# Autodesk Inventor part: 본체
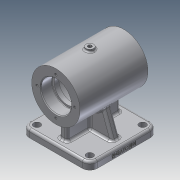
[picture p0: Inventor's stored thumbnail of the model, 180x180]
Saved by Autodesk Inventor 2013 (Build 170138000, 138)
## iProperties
Created: 2019-06
Part Number: 본체
Material: 알루미늄 6061
Document SubType Name: Modeling
Designer: user
Density: 2.71 g/cm^3
Mass: 612.634 g
Surface Area: 622.719 cm^2
Volume: 226.064 cm^3
Author: user
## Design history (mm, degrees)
sketch "스케치1"
  geometry: C1 r 32 at (0, 0); 1 further point
  constraints: 1 centre point, 1 coincident
  dimensions: "d0" = 64 diameter of C1
extrude "돌출1" new body sketch "스케치1" stored distance "d1" = 90; taper "d2" = 0 deg
sketch "스케치2"
  geometry: L1 (32, 45)-(-32, 45) reference; L2 (-32, -45)-(32, -45) reference; L3 (0, 45)-(0, -45); L4 (20, 45)-(20, 30); L5 (20, 30)-(17, 30); L6 (17, 30)-(17, 24); L7 (17, 24)-(25, 24); L8 (25, 24)-(25, -24); L9 (25, -24)-(17, -24); L10 (17, -24)-(17, -30); L11 (17, -30)-(20, -30); L12 (20, -30)-(20, -45); 1 further point
  constraints: 20 end point, 5 perpendicular, 4 parallel, 2 midpoint, 2 point on line
  dimensions: "d3" = 15 distance of L4.start L4.end; "d5" = 15 distance of L11.end L12.end; "d6" = 6 distance of L5.end L6.end; "d7" = 6 distance of L9.end L10.end; "d8" = 40 diameter of L4 L3; "d9" = 40 diameter of L12 L3; "d10" = 50 diameter of L8 L3; "d11" = 34 diameter of L6 L3; "d12" = 34 diameter of L10 L3
revolve "회전1" sketch "스케치2" stored, may be unused: angle "d13" = 90 deg
chamfer "모따기1" distance "d14" = 1; stored, may be unused: second distance "d15" = 2, angle "d16" = 45 deg
fillet "모깎기1" dims "d17" = 3
fillet "모깎기2" dims "d18" = 0.6
sketch "스케치3"
  geometry: L1 (0, 0)-(0, 25); C1 r 21 at (0, 0) reference; 1 further point
  constraints: 2 end point, 1 coincident, 1 vertical
  dimensions: "d19" = 25 distance of L1.start L1.end
hole "구멍1" sketch "스케치3" at (0, 25) diameter "d20" = 3.242; stored, may be unused: countersink angle "d24" = 90 deg, drill point angle "d26" = 118 deg; dims "d21" = 7, "d22" = 4, "d23" = 2, "d25" = 9
node "작업 평면1"
sketch "스케치4"
  geometry: L1 (45, -45)-(-45, -45); L2 (-45, -45)-(-45, 45); L3 (-45, 45)-(45, 45); L4 (45, 45)-(45, -45); L5 (45, -45)-(-45, 45); L6 (-45, -45)-(45, 45); 1 further point
  constraints: 12 end point, 2 midpoint, 2 parallel, 1 horizontal, 1 perpendicular
  dimensions: "d31" = 90 distance of L2.end L3.end; "d32" = 90 distance of L1.end L2.end
extrude "돌출2" join sketch "스케치4" distance "d33" = 10; taper "d34" = 0 deg
fillet "모깎기3" dims "d35" = 10
sketch "스케치5"
  geometry: A1 r 10 centre (-35, -35) between (-45, -35) and (-35, -45) reference; A2 r 10 centre (35, -35) between (35, -45) and (45, -35) reference; A3 r 10 centre (35, 35) between (45, 35) and (35, 45) reference; A4 r 10 centre (-35, 35) between (-35, 45) and (-45, 35) reference; 5 further points
  constraints: 4 coincident
hole "구멍2" sketch "스케치5" at (-35, 35), (35, 35), (35, -35), (-35, -35) diameter "d36" = 9; stored, may be unused: countersink angle "d40" = 90 deg, drill point angle "d42" = 118 deg; dims "d37" = 7, "d38" = 4, "d39" = 2, "d41" = 9
sketch "스케치6"
  geometry: L1 (5, -35)-(-5, -35); L2 (-5, -35)-(-5, 35); L3 (-5, 35)-(5, 35); L4 (5, 35)-(5, -35); L5 (5, -35)-(-5, 35); L6 (-5, -35)-(5, 35); 1 further point
  constraints: 12 end point, 2 midpoint, 2 parallel, 1 horizontal, 1 perpendicular
  dimensions: "d43" = 10 distance of L2.end L3.end; "d44" = 70 distance of L1.end L2.end
extrude "돌출3" join sketch "스케치6" stored distance "d45" = 10; taper "d46" = 0 deg
sketch "스케치7"
  geometry: L1 (35, -55)-(-35, -55) reference; L2 (23.058, -22.189)-(35, -55); L3 (45, -55)-(45, -65) reference; 2 further points
  constraints: 2 end point, 1 point on line, 2 other
  dimensions: "d47" = 110 deg angle of L1 L2; "d48" = 10 distance of L3.start L2.end
feature "리브1" sketch "스케치7" dims "d49" = 1, "d50" = 10, "d51" = 0, "d52" = 0, "d53" = 1, "d54" = 1
node "작업 평면2"
sketch "스케치8"
  geometry: C1 r 5 at (0, 0); 1 further point
  constraints: 1 centre point, 1 coincident
  dimensions: "d56" = 10 diameter of C1
extrude "돌출4" join sketch "스케치8" stored distance "d57" = 10; taper "d58" = 0 deg
sketch "스케치9"
  geometry: C1 r 5 at (0, 0) reference; 1 further point
  constraints: 1 coincident
hole "구멍3" sketch "스케치9" at (0, 0) diameter "d59" = 4.917; stored, may be unused: countersink angle "d63" = 90 deg, drill point angle "d65" = 118 deg; dims "d60" = 20, "d61" = 4, "d62" = 2, "d64" = 9
fillet "모깎기4" dims "d66" = 2
sketch "스케치11"
  geometry: L1 (40, -40)-(-40, -40); L2 (-40, -40)-(-40, 40); L3 (-40, 40)-(40, 40); L4 (40, 40)-(40, -40); C1 r 4.5 at (-35, 35) reference; C2 r 4.5 at (35, -35) reference; C3 r 4.5 at (-35, -35) reference; C4 r 4.5 at (35, 35) reference; 3 further points
  constraints: 8 end point, 2 midpoint, 2 parallel, 1 horizontal, 1 horizontal alignment, 1 perpendicular, 1 vertical alignment
  dimensions: "d73" = 80 distance of L2.end L3.end; "d74" = 80 distance of L1.end L2.end
extrude "돌출5" cut sketch "스케치11" distance "d76" = 5; taper "d77" = 0 deg
sketch "스케치12"
  geometry: C1 r 4.5 at (35, 35) reference; C2 r 4.5 at (-35, -35) reference; C3 r 4.5 at (35, -35) reference; C4 r 4.5 at (-35, 35) reference; C5 r 10 at (35, -35); C6 r 10 at (-35, -35); C7 r 10 at (-35, 35); C8 r 10 at (35, 35); 1 further point
  constraints: 4 centre point, 4 coincident
  dimensions: "d78" = 20 diameter of C5; "d79" = 20 diameter of C6; "d80" = 20 diameter of C7; "d81" = 20 diameter of C8
extrude "돌출6" join sketch "스케치12" distance "d82" = 5; taper "d83" = 0 deg
fillet "모깎기5" dims "d84" = 3
fillet "모깎기6" dims "d85" = 3
fillet "모깎기7" dims "d86" = 3
fillet "모깎기8" dims "d87" = 3
fillet "모깎기9" dims "d88" = 3
sketch "스케치13"
  geometry: L1 (-10, 7)-(-10, 0) reference; 2 further points
  constraints: 1 other
  dimensions: "d89" = 45 distance from line of L1 point (35, 4); "d90" = 4 vertical distance of L1.end point (35, 4)
feature "엠보싱1" sketch "스케치13" dims "d91" = 0.5, "d92" = 0
node "솔리드1"
pattern_circular "원형 패턴1" dims angle "d28" = 360 deg
mirror "대칭1"
mirror "대칭2"
other parameters: "d30" = -65
